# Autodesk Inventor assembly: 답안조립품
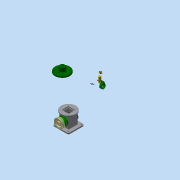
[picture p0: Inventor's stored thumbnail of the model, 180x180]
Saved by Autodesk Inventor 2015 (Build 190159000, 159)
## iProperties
Created: 2021-05
Part Number: 답안조립품
Document SubType Name: Assembly
Designer: 102879
Author: 102879
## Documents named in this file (19)
- C:\Users\102879\Desktop\710506V1011\답안조립품.iam
- C:\Users\102879\Desktop\710506V1011\본체.ipt
- C:\Users\102879\Desktop\710506V1011\E-링.ipt
- C:\Users\102879\Desktop\710506V1011\V-벨트풀리.ipt
- C:\Users\102879\Desktop\710506V1011\덮개.ipt
- C:\Users\102879\Desktop\710506V1011\뒤커버.ipt
- C:\Users\102879\Desktop\710506V1011\링크.ipt
- C:\Users\102879\Desktop\710506V1011\베어링 17 x 40 x 12.ipt
- C:\Users\102879\Desktop\710506V1011\볼트 M4 x 10.ipt
- C:\Users\102879\Desktop\710506V1011\볼트 M4 x 12.ipt
- 볼트 M4 x 12.ipt
- C:\Users\102879\Desktop\710506V1011\슬라이더.ipt
- C:\Users\102879\Desktop\710506V1011\앞커버.ipt
- C:\Users\102879\Desktop\710506V1011\오일 실 17 30 8.ipt
- C:\Users\102879\Desktop\710506V1011\와셔 4x16.ipt
- C:\Users\102879\Desktop\710506V1011\클레비스 핀 6 x 22.ipt
- 클레비스 핀 6 x 22.ipt
- C:\Users\102879\Desktop\710506V1011\키 4 x 4 x 12.ipt
- C:\Users\102879\Desktop\710506V1011\편심축.ipt
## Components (2 placed, 2 different names)
1. E-링:1
2. V-벨트풀리:1
